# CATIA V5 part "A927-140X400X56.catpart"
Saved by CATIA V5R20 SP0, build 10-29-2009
Part number: A927-140X400X56
Source: Unknown
Property "A": "90.000"
Property "ARTICLENO": "A927-140X400X56"
Property "BOMINFO": "A927-140X400X56"
Property "CODE": "A927-140X400X56"
Property "CREATOR": "CADENAS GmbH"
Property "D": "22.000"
Property "D1": "33.000"
Property "F": "36.000"
Property "FORM": "B"
Property "L": "400.000"
Property "L1": "150.000"
Property "L2": "40.000"
Property "L3": "80.000"
Property "LINA": "A927-140X400X56"
Property "NB": "A927-140X400X56"
Property "NBSYN": "$CODE."
Property "NN": "A927"
Property "NT": "VDI 3387 Removable Die Heels, steel and self-lubricating"
Property "R": "31.500"
Property "S": "56.000"
Property "SUPPLIER": "CF"
Property "T": "25.500"
Property "W": "140.000"
Bounding box of the stored display mesh (mm): x -70 to 70, y 0 to 400, z -56 to 0
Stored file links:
  C:\Users\borellobunino\Desktop\3D X SITO CF\A927\GSB_OILLESS_G2290514040056\CATIAV5\A927-140X400X56.catpart
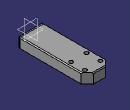
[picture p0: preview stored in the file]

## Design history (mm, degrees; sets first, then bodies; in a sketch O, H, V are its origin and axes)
Body1 "Geometry.1" (main body)
  Solid1 "A927-140X400X56.catpart": solid without history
